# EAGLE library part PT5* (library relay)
Miniature Relay SCHRACK 2 pole 12 A, 3 pole 10 A or 4 pole 6 A DC- or AC-coil Source: http://www.schrack.com/.. 5823.pdf Socked 78604 Source: http://www.schrack.com/.. 5836.pdf
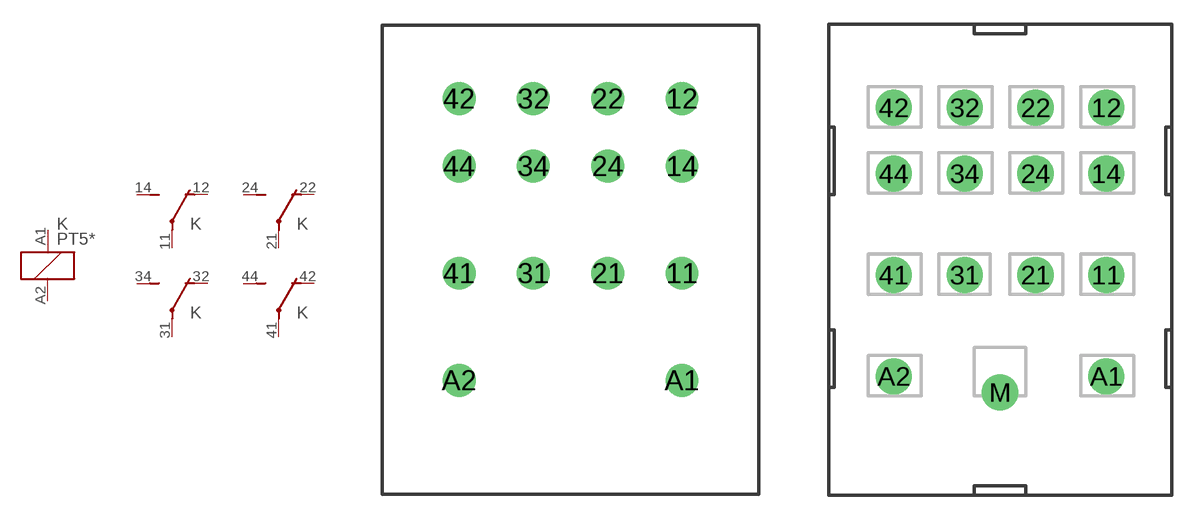
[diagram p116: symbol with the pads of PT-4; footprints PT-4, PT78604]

Designator prefix K; gates 1=K 2=U 3=U 4=U 5=U

## PT571R06 (OC_FARNELL: unknown; OC_NEWARK: unknown), PT571R12 (OC_FARNELL: unknown; OC_NEWARK: unknown), PT571R24 (OC_FARNELL: unknown; OC_NEWARK: unknown), PT571R48 (OC_FARNELL: unknown; OC_NEWARK: unknown), PT571R60 (OC_FARNELL: unknown; OC_NEWARK: unknown), PT571S15 (OC_FARNELL: unknown; OC_NEWARK: unknown), PT571T30 (OC_FARNELL: unknown; OC_NEWARK: unknown), PT581R06 (OC_FARNELL: unknown; OC_NEWARK: unknown), PT581R12 (OC_FARNELL: unknown; OC_NEWARK: unknown), PT581R24 (OC_FARNELL: unknown; OC_NEWARK: unknown), PT581R48 (OC_FARNELL: unknown; OC_NEWARK: unknown), PT581R60 (OC_FARNELL: unknown; OC_NEWARK: unknown), PT581S15 (OC_FARNELL: unknown; OC_NEWARK: unknown), PT581T30 (OC_FARNELL: unknown; OC_NEWARK: unknown), PT571506 (OC_FARNELL: unknown; OC_NEWARK: unknown), PT571512 (OC_FARNELL: unknown; OC_NEWARK: unknown), PT571524 (MF: FARNELL; MPN: PT571524; OC_FARNELL: 3072836; OC_NEWARK: 08J0830), PT571548 (OC_FARNELL: unknown; OC_NEWARK: unknown), PT571560 (OC_FARNELL: unknown; OC_NEWARK: unknown), PT571615 (MF: FARNELL; MPN: PT571615; OC_FARNELL: 3072990; OC_NEWARK: 85H0667), PT571730 (MF: FARNELL; MPN: PT571730; OC_FARNELL: 3073014; OC_NEWARK: 18J8266), PT581506 (OC_FARNELL: unknown; OC_NEWARK: unknown), PT581512 (OC_FARNELL: unknown; OC_NEWARK: unknown), PT581524 (OC_FARNELL: unknown; OC_NEWARK: unknown), PT581548 (OC_FARNELL: unknown; OC_NEWARK: unknown), PT581560 (OC_FARNELL: unknown; OC_NEWARK: unknown), PT581615 (OC_FARNELL: unknown; OC_NEWARK: unknown), PT581730 (OC_FARNELL: unknown; OC_NEWARK: unknown)  [PT-4]
11  2:P  pas
12  2:O  pas
14  2:S  pas
21  3:P  pas
22  3:O  pas
24  3:S  pas
31  4:P  pas
32  4:O  pas
34  4:S  pas
41  5:P  pas
42  5:O  pas
44  5:S  pas
A1  1:1  pas
A2  1:2  pas

## PT5-78604 (OC_FARNELL: unknown; OC_NEWARK: unknown)  [PT78604]
Pads as for PT-4

## Footprint PT-4 (pad centres in mm)
Miniature Relay SCHRACK 4 pole 6 A DC- or AC-coil Source: http://www.schrack.com/.. 5823.pdf
drill 1.3 round: 11 6.6,6.35; 12 6.6,16.7; 14 6.6,12.7; 21 2.2,6.35; 22 2.2,16.7; 24 2.2,12.7; 31 -2.2,6.35; 32 -2.2,16.7; 34 -2.2,12.7; 41 -6.6,6.35; 42 -6.6,16.7; 44 -6.6,12.7; A1 6.6,0; A2 -6.6,0

## Footprint PT78604 (pad centres in mm)
Accessories Miniature Relay PT SCHRACK Socket with PCB terminals 4 Pol. Source: http://www.schrack.com/.. 5836.pdf
drill 1.5 round: 11 6.6,6.3; 12 6.6,16.7; 14 6.6,12.6; 21 2.2,6.3; 22 2.2,16.7; 24 2.2,12.6; 31 -2.2,6.3; 32 -2.2,16.7; 34 -2.2,12.6; 41 -6.6,6.3; 42 -6.6,16.7; 44 -6.6,12.6; A1 6.6,0; A2 -6.6,0; M 0,-1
